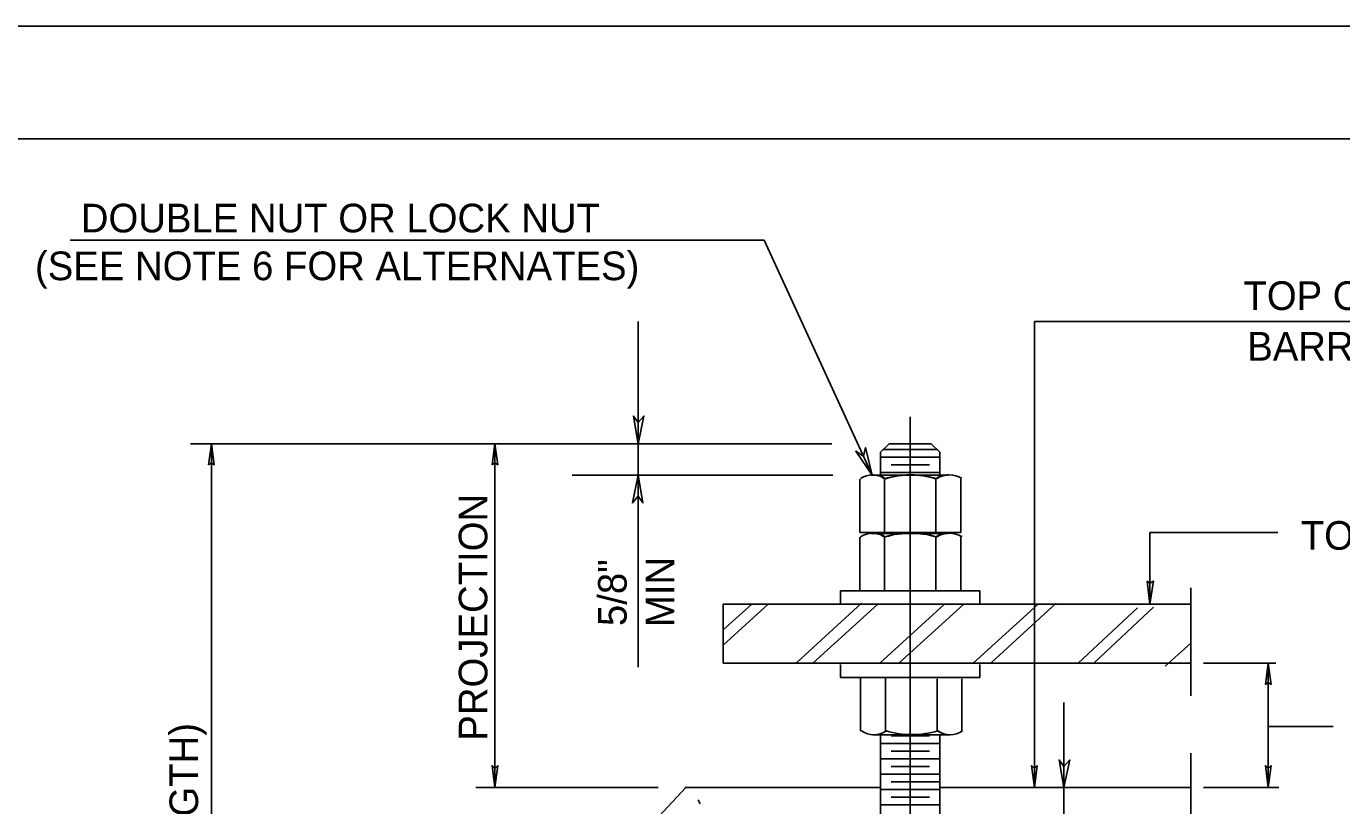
# Model space of a CAD drawing. Extents: x -3 to 26050223, y 0 to 12035012.
# Drawn here: x 15.59 to 27.07, y 36.52 to 43.33 of the extents above; entities that cross this region are included whole.
import ezdxf

# ---------------------------------------------------------------- set-up
doc = ezdxf.new("R2010")
doc.units = 0
for name, color, linetype in [('1', 7, 'Continuous'), ('2', 7, 'Continuous'), ('39', 7, 'Continuous')]:
    doc.layers.add(name, color=color, linetype=linetype)

msp = doc.modelspace()

# ---------------------------------------------------------------- linework, layer by layer
at = {"layer": '1'}
for p, q in [((68.892, 43.325), (0, 43.325)), ((68.183, 42.342), (3.6, 42.342)), ((23.308, 39.917), (23.308, 31.075)), ((23.05, 39.608), (23.125, 39.683)), ((23.542, 39.633), (23.075, 39.633)), ((23.125, 39.683), (23.492, 39.683)), ((23.567, 39.608), (23.492, 39.683)), ((23.533, 39.633), (23.533, 39.633)), ((23.05, 39.608), (23.05, 39.4)), ((23.533, 39.567), (23.533, 39.567)), ((23.567, 39.608), (23.567, 39.392)), ((23.625, 39.408), (22.967, 39.408)), ((22.975, 39.408), (23.633, 39.408)), ((23.533, 39.408), (23.517, 39.408)), ((23.533, 39.433), (23.533, 39.433)), ((23.533, 39.408), (23.533, 39.408)), ((22.867, 39.375), (22.867, 38.908)), ((23.083, 39.375), (23.083, 38.908)), ((23.533, 39.375), (23.533, 38.908)), ((23.533, 39.3), (23.533, 39.3)), ((23.75, 39.375), (23.75, 38.908)), ((23.533, 39.167), (23.533, 39.167)), ((23.533, 39.033), (23.533, 39.033)), ((23.75, 38.908), (22.867, 38.908)), ((22.867, 38.867), (22.867, 38.4)), ((23.625, 38.9), (22.967, 38.9)), ((22.975, 38.9), (23.633, 38.9)), ((23.083, 38.867), (23.083, 38.4)), ((23.533, 38.9), (23.517, 38.9)), ((23.533, 38.9), (23.533, 38.9)), ((23.533, 38.867), (23.533, 38.4)), ((23.75, 38.867), (23.75, 38.4)), ((22.7, 38.283), (22.7, 38.4)), ((22.7, 38.4), (23.308, 38.4)), ((23.308, 38.4), (23.917, 38.4)), ((23.917, 38.4), (23.917, 38.283)), ((21.675, 38.283), (25.758, 38.283)), ((21.675, 38.283), (21.675, 37.767)), ((21.675, 37.767), (25.75, 37.767)), ((22.7, 37.758), (22.7, 37.642)), ((23.917, 37.642), (23.917, 37.758)), ((22.7, 37.642), (23.308, 37.642)), ((22.875, 37.175), (22.875, 37.642)), ((23.092, 37.175), (23.092, 37.642)), ((23.308, 37.642), (23.917, 37.642)), ((23.542, 37.175), (23.542, 37.633)), ((23.758, 37.175), (23.758, 37.633)), ((23.542, 37.208), (23.542, 37.208)), ((23.55, 37.275), (23.55, 37.275)), ((23.65, 37.142), (22.983, 37.142)), ((23.642, 37.142), (22.983, 37.142)), ((23.05, 37.15), (23.05, 35.133)), ((23.567, 37.142), (23.567, 35.133)), ((21.117, 36.433), (21.35, 36.683)), ((21.342, 36.683), (23.05, 36.683)), ((23.567, 36.683), (25.758, 36.683))]:
    msp.add_line(p, q, dxfattribs=at)
for points in [[(20.933, 39.683), (20.983, 39.925), (20.933, 39.867), (20.892, 39.925)], [(22.975, 39.408), (22.917, 39.65), (22.9, 39.575), (22.833, 39.617)], [(20.933, 39.408), (20.883, 39.167), (20.933, 39.225), (20.975, 39.167)], [(25.4, 38.467), (25.433, 38.483), (25.4, 38.283), (25.375, 38.483)], [(24.65, 36.683), (24.7, 36.925), (24.65, 36.867), (24.608, 36.925)]]:
    msp.add_lwpolyline(points, close=True, dxfattribs=at)
for centre, radius, start, end in [((22.982, 39.22), 0.192, 55.6284, 124.4174), ((22.974, 39.22), 0.192, 55.6284, 90), ((23.307, 38.635), 0.776, 73.1289, 106.8539), ((23.316, 38.635), 0.776, 73.1289, 106.8539), ((23.641, 39.22), 0.192, 90, 124.3065), ((23.649, 39.22), 0.192, 55.5826, 124.3065), ((23.307, 38.311), 1.1, 77.7537, 77.7623), ((23.991, 38.311), 1.1, 102.2377, 102.2463), ((22.982, 38.711), 0.192, 55.6284, 124.4174), ((22.974, 38.711), 0.192, 55.6284, 90), ((23.307, 38.127), 0.776, 73.1289, 106.8539), ((23.316, 38.127), 0.776, 73.1289, 106.8539), ((23.641, 38.711), 0.192, 90, 124.3065), ((23.649, 38.711), 0.192, 55.5826, 124.3065), ((23.307, 37.803), 1.1, 77.7537, 77.7623), ((23.991, 37.803), 1.1, 102.2377, 102.2463), ((22.991, 37.336), 0.192, 235.5826, 304.3716), ((22.991, 37.336), 0.192, 270, 304.3716), ((23.324, 37.921), 0.776, 253.1461, 286.8711), ((23.324, 37.921), 0.776, 253.1461, 286.8711), ((23.657, 37.336), 0.192, 235.6935, 304.4174), ((23.657, 37.336), 0.192, 235.6935, 270), ((23.316, 38.245), 1.1, 282.2377, 282.2463)]:
    msp.add_arc(centre, radius, start, end, dxfattribs=at)
at = {"layer": '2'}
for p, q in [((22.033, 41.458), (15.975, 41.458)), ((22.975, 39.408), (22.033, 41.458)), ((20.933, 39.683), (20.933, 40.75)), ((24.392, 36.683), (24.392, 40.75)), ((24.392, 40.75), (30.433, 40.75)), ((17.025, 39.683), (22.625, 39.683)), ((17.092, 39.683), (20.433, 39.683)), ((17.208, 39.683), (17.208, 35.483)), ((19.683, 39.683), (19.683, 36.683)), ((20.933, 39.408), (20.933, 39.683)), ((23.567, 39.567), (23.05, 39.567)), ((23.475, 39.5), (23.142, 39.5)), ((20.358, 39.408), (22.633, 39.408)), ((20.933, 37.733), (20.933, 39.408)), ((23.567, 39.433), (23.05, 39.433)), ((25.4, 38.283), (25.4, 38.908)), ((25.4, 38.908), (26.517, 38.908)), ((25.758, 38.425), (25.758, 37.483)), ((21.675, 38.058), (21.925, 38.283)), ((21.675, 37.925), (22.067, 38.283)), ((22.317, 37.775), (22.883, 38.292)), ((22.458, 37.767), (23.025, 38.283)), ((23.042, 37.767), (23.608, 38.283)), ((23.208, 37.767), (23.775, 38.283)), ((23.858, 37.767), (24.425, 38.283)), ((24.017, 37.775), (24.583, 38.292)), ((24.775, 37.767), (25.292, 38.25)), ((24.917, 37.775), (25.433, 38.258)), ((25.533, 37.742), (25.758, 37.942)), ((22.7, 37.767), (23.308, 37.767)), ((23.917, 37.767), (23.308, 37.767)), ((25.867, 37.767), (26.5, 37.767)), ((26.433, 37.767), (26.433, 36.683)), ((24.65, 36.683), (24.65, 37.425)), ((26.433, 37.217), (27, 37.217)), ((23.475, 37.133), (23.142, 37.133)), ((23.542, 37.142), (23.542, 37.142)), ((23.567, 37.067), (23.05, 37.067)), ((23.475, 37), (23.142, 37)), ((23.533, 37.067), (23.533, 37.067)), ((23.542, 37.075), (23.542, 37.075)), ((23.542, 37.075), (23.542, 37.075)), ((25.758, 36.983), (25.758, 36.233)), ((23.567, 36.933), (23.05, 36.933)), ((23.475, 36.867), (23.142, 36.867)), ((23.533, 36.933), (23.533, 36.933)), ((23.567, 36.8), (23.05, 36.8)), ((23.567, 36.8), (23.05, 36.8)), ((23.533, 36.8), (23.533, 36.8)), ((23.533, 36.8), (23.533, 36.8)), ((19.517, 36.683), (21.108, 36.683)), ((23.567, 36.667), (23.05, 36.667)), ((23.567, 36.733), (23.142, 36.733)), ((23.533, 36.733), (23.533, 36.733)), ((23.533, 36.667), (23.533, 36.667)), ((24.65, 36.267), (24.65, 36.683)), ((25.867, 36.683), (26.525, 36.683)), ((21.475, 36.542), (21.458, 36.575)), ((23.567, 36.533), (23.05, 36.533)), ((23.475, 36.6), (23.142, 36.6)), ((23.533, 36.533), (23.533, 36.533))]:
    msp.add_line(p, q, dxfattribs=at)
for points in [[(17.183, 39.5), (17.208, 39.683), (17.233, 39.5), (17.208, 39.517)], [(19.658, 39.5), (19.683, 39.683), (19.708, 39.5), (19.683, 39.517)], [(26.408, 37.583), (26.433, 37.767), (26.458, 37.583), (26.433, 37.6)], [(19.708, 36.875), (19.683, 36.683), (19.658, 36.875), (19.683, 36.85)], [(24.417, 36.875), (24.392, 36.683), (24.367, 36.875), (24.392, 36.85)], [(26.458, 36.875), (26.433, 36.683), (26.408, 36.875), (26.433, 36.85)]]:
    msp.add_lwpolyline(points, close=True, dxfattribs=at)

# ---------------------------------------------------------------- texts
at = {"layer": '39'}
for s, p in [('DOUBLE NUT OR LOCK NUT', (16.068, 41.527)), ('(SEE NOTE 6 FOR ALTERNATES)', (15.668, 41.11)), ('TOP OF PEDESTAL OR', (26.217, 40.85)), ('BARRIER PEDESTAL', (26.25, 40.408)), ('TOP OF BASE PLATE', (26.717, 38.758))]:
    msp.add_text(s, height=0.25, dxfattribs=at).set_placement(p)
for s, height, p in [('PROJECTION', 0.2499, (19.617, 37.092)), ('5/8"', 0.2499, (20.833, 38.092)), ('MIN', 0.2499, (21.25, 38.083)), ('BOLT LENGTH (LGTH)', 0.25, (17.092, 33.717))]:
    msp.add_text(s, height=height, rotation=90, dxfattribs=at).set_placement(p)

doc.saveas('drawing.dxf')
